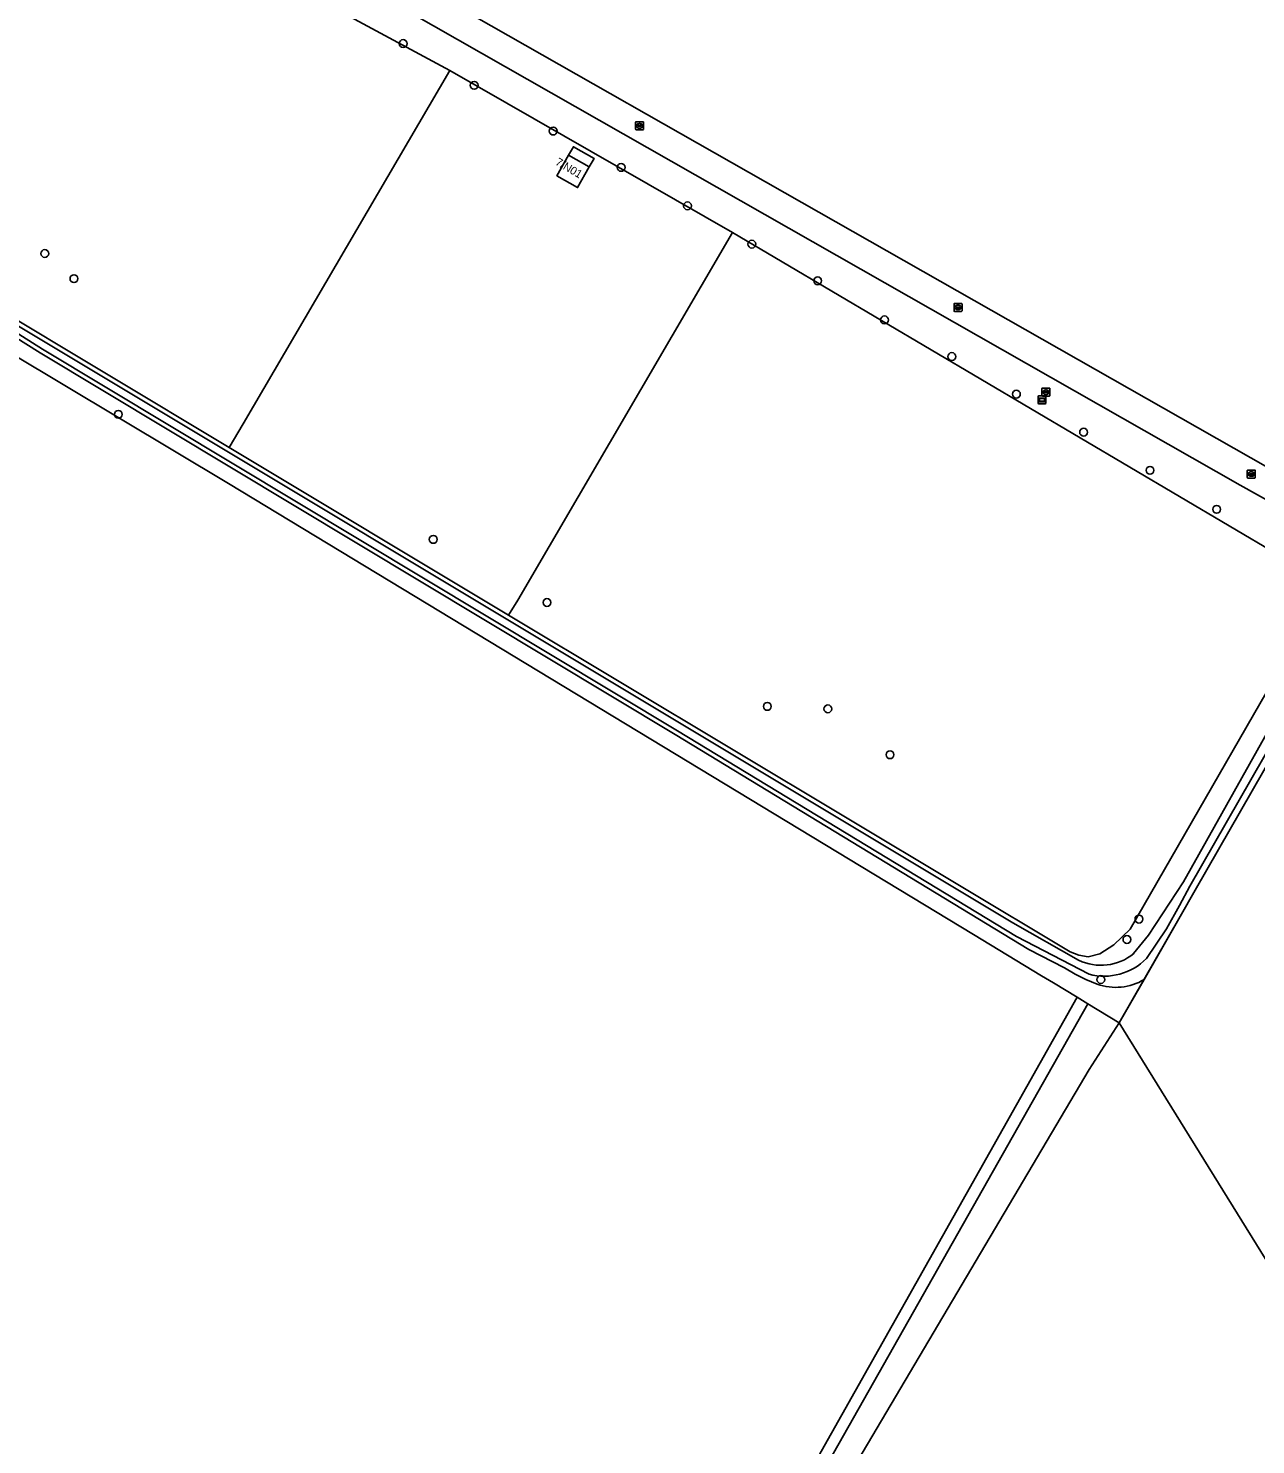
# Model space of a CAD drawing. Extents: x 156502 to 159075, y 384229 to 386100.
# Drawn here: x 157006.8 to 157160.1, y 385363.6 to 385540.6 of the extents above; entities that cross this region are included whole.
import ezdxf

# ---------------------------------------------------------------- set-up
doc = ezdxf.new("R2010")
doc.units = 0
for name, color, linetype in [('IMGEO_Berm_groen', 7, 'Continuous'), ('IMGEO_Boom', 7, 'Continuous'), ('IMGEO_Brandkraan', 7, 'Continuous'), ('IMGEO_Gemengd_bos', 7, 'Continuous'), ('IMGEO_Grasland_agrarisch', 7, 'Continuous'), ('IMGEO_Greppel_droge_sloot', 7, 'Continuous'), ('IMGEO_Groenvoorziening', 7, 'Continuous'), ('IMGEO_Hek', 7, 'Continuous'), ('IMGEO_Loofbos', 7, 'Continuous'), ('IMGEO_Oever', 7, 'Continuous'), ('IMGEO_Pand', 7, 'Continuous'), ('IMGEO_Pand_nummerreeks', 7, 'Continuous'), ('IMGEO_Rijbaan_lokaal_gesloten', 7, 'Continuous'), ('IMGEO_Rioolput', 7, 'Continuous'), ('IMGEO_Verklikker', 7, 'Continuous'), ('IMGEO_Voetpad_open', 7, 'Continuous'), ('IMGEO_Waterloop', 7, 'Continuous')]:
    doc.layers.add(name, color=color, linetype=linetype)

msp = doc.modelspace()

# ---------------------------------------------------------------- linework, layer by layer
at = {"layer": 'IMGEO_Berm_groen'}
msp.add_lwpolyline([(157001.03, 385573.03), (156996.31, 385575.65), (156994.07, 385576.9), (156991.33, 385572.02), (157059.48, 385535.3), (157094.76, 385515.05), (157169.19, 385471.06), (157172.1, 385476.13), (157162.51, 385481.09), (157158.15, 385483.48)], close=True, dxfattribs=at)
at = {"layer": 'IMGEO_Boom'}
for centre in [(157053.64, 385538.65), (157062.51, 385533.44), (157072.38, 385527.72), (157080.86, 385523.18), (157089.15, 385518.38), (157008.89, 385512.42), (157097.18, 385513.6), (157012.53, 385509.29), (157105.4, 385509.02), (157113.75, 385504.13), (157122.16, 385499.55), (157130.22, 385494.86), (157018.07, 385492.33), (157138.61, 385490.1), (157146.9, 385485.34), (157155.23, 385480.47), (157057.4, 385476.71), (157071.6, 385468.83), (157099.12, 385455.85), (157106.68, 385455.54), (157114.44, 385449.81), (157145.52, 385429.28), (157144.02, 385426.73), (157140.76, 385421.73)]:
    msp.add_circle(centre, 0.489, dxfattribs=at)
at = {"layer": 'IMGEO_Brandkraan'}
for p, q in [((157133.41, 385494.68), (157133.41, 385495.53)), ((157133.48, 385495.6), (157134.34, 385495.6)), ((157133.67, 385495.1), (157133.67, 385495.11)), ((157133.71, 385495.15), (157134.11, 385495.15)), ((157134.11, 385495.06), (157133.71, 385495.06)), ((157133.9, 385495.38), (157133.92, 385495.38)), ((157133.92, 385494.82), (157133.9, 385494.82)), ((157134.15, 385495.11), (157134.15, 385495.1)), ((157134.41, 385495.53), (157134.41, 385494.68)), ((157134.34, 385494.6), (157133.48, 385494.6))]:
    msp.add_line(p, q, dxfattribs=at)
for points in [[(157133.41, 385494.68), (157133.41, 385495.53)], [(157133.48, 385495.6), (157134.34, 385495.6)], [(157134.41, 385495.53), (157134.41, 385494.68)], [(157134.34, 385494.6), (157133.48, 385494.6)]]:
    msp.add_lwpolyline(points, dxfattribs=at)
for centre, radius, start, end in [((157133.49, 385495.53), 0.0765, 91.552, 178.448), ((157133.49, 385495.53), 0.0765, 91.552, 178.448), ((157133.71, 385495.11), 0.0403, 85.8775, 175.7526), ((157133.71, 385495.1), 0.0366, 178.938, 274.7102), ((157134.11, 385495.11), 0.0386, 1.7309, 96.639), ((157134.11, 385495.1), 0.043, 264.8664, 352.4533), ((157134.33, 385495.53), 0.0765, 1.552, 88.448), ((157134.33, 385495.53), 0.0765, 1.552, 88.448), ((157133.49, 385494.68), 0.0765, 181.552, 268.448), ((157133.49, 385494.68), 0.0765, 181.552, 268.448), ((157134.33, 385494.68), 0.0765, 271.552, 358.448), ((157134.33, 385494.68), 0.0765, 271.552, 358.448)]:
    msp.add_arc(centre, radius, start, end, dxfattribs=at)
for centre, major_axis, ratio, start_param, end_param in [((157133.9, 385495.1), (-0.387, 0.002), 0.722429, 4.712389, 7.853982), ((157133.92, 385495.1), (-0.39, 0.002), 0.717154, 1.570796, 4.712389)]:
    msp.add_ellipse(centre, major_axis=major_axis, ratio=ratio, start_param=start_param, end_param=end_param, dxfattribs=at)
at = {"layer": 'IMGEO_Gemengd_bos'}
msp.add_lwpolyline([(157191.03, 385500), (157152.55, 385432.88), (157150.67, 385429.59), (157146.17, 385421.74), (157143.05, 385416.31), (157168.42, 385375.4)], dxfattribs=at)
at = {"layer": 'IMGEO_Grasland_agrarisch'}
msp.add_lwpolyline([(157014.02, 385600.24), (157004.36, 385586.62), (157002.14, 385583.66), (156998.46, 385578.63), (156999.74, 385577.82), (157163.72, 385484.49)], dxfattribs=at)
at = {"layer": 'IMGEO_Greppel_droge_sloot'}
for points in [[(157393.36, 385858.05), (157393.11, 385857.61), (157362.75, 385804.11), (157325.82, 385739.17), (157293.92, 385684.22), (157277.51, 385655.56), (157259.26, 385623.71), (157238.62, 385587.75), (157224.85, 385563.79), (157203.07, 385525.9), (157174.27, 385475.36), (157161.25, 385452.05), (157151.08, 385433.93), (157146.7, 385427.27), (157144.86, 385424.97)], [(157146.46, 385424.36), (157148.98, 385428.05), (157150.58, 385430.99), (157151.89, 385433.4), (157190.31, 385500.41), (157270.67, 385640.6), (157287.16, 385669.09), (157334.24, 385750.41), (157371.86, 385817.15), (157394.6, 385857.47)], [(156957.24, 385534.77), (156969.36, 385548.57), (156968.77, 385549.2), (156968.26, 385549.73), (156953.85, 385533.85), (156962.21, 385528.96), (156977.13, 385519.65), (157000.29, 385505.71), (157008.62, 385500.48), (157087.91, 385452.8), (157130.24, 385427.09), (157139.29, 385422.4)], [(157137.99, 385424.15), (157129.78, 385428.82), (157066.52, 385466.78), (157031.64, 385487.72), (156971.16, 385524.01), (156960.67, 385530.59), (156958.05, 385532.14)]]:
    msp.add_lwpolyline(points, dxfattribs=at)
for centre, radius, start, end in [((157140.78, 385429.95), 6.44, 244.2682, 309.3516), ((157141.2, 385429.51), 7.36, 254.9937, 315.6328)]:
    msp.add_arc(centre, radius, start, end, dxfattribs=at)
at = {"layer": 'IMGEO_Groenvoorziening'}
for points in [[(157059.48, 385535.3), (156991.33, 385572.02), (156989.98, 385570.43), (156975.63, 385554.48), (156970.11, 385548.59), (156957.68, 385534.42)], [(157008.33, 385500), (157000, 385505.23), (156976.84, 385519.18), (156961.92, 385528.48), (156952.97, 385533.71), (156952.57, 385531.03), (156952.99, 385531.11), (156953.52, 385530.93), (157000, 385502.8), (157002.27, 385501.42), (157004.67, 385499.97), (157031.83, 385483.7), (157124.85, 385427.36), (157133.37, 385422.2), (157134.84, 385421.31), (157137.81, 385419.52), (157139.14, 385418.7), (157143.05, 385416.31), (157146.17, 385421.74)], [(156958.28, 385532.65), (156960.96, 385531.06), (156971.45, 385524.49), (157031.92, 385488.2), (157033.65, 385491.16), (157059.48, 385535.3)], [(157140.31, 385421.15), (157138.9, 385421.73), (157137.54, 385422.42), (157136.21, 385423.18), (157131.79, 385425.5), (157087.62, 385452.33), (157008.33, 385500)]]:
    msp.add_lwpolyline(points, dxfattribs=at)
msp.add_lwpolyline([(157169.19, 385471.06), (157094.76, 385515.05), (157067.95, 385469.14), (157066.81, 385467.26), (157136.95, 385425.17), (157138.03, 385424.77), (157139.2, 385424.57), (157140.63, 385424.94), (157142.39, 385426.07), (157144.41, 385428.01)], close=True, dxfattribs=at)
msp.add_arc((157142.62, 385427.61), 6.86, 250.3239, 301.1457, dxfattribs=at)
at = {"layer": 'IMGEO_Hek'}
for points in [[(157004.67, 385499.97), (157031.83, 385483.7), (157124.85, 385427.36)], [(157191.03, 385500), (157152.55, 385432.88)], [(157152.55, 385432.88), (157150.67, 385429.59)], [(157150.67, 385429.59), (157143.05, 385416.31)], [(157124.85, 385427.36), (157133.37, 385422.2)], [(157051.69, 385266.61), (157137.81, 385419.52)], [(157137.81, 385419.52), (157139.14, 385418.7)], [(157143.05, 385416.31), (157139.14, 385418.7)]]:
    msp.add_lwpolyline(points, dxfattribs=at)
at = {"layer": 'IMGEO_Loofbos'}
for points in [[(157094.76, 385515.05), (157059.48, 385535.3), (157033.65, 385491.16), (157031.92, 385488.2), (157066.81, 385467.26), (157067.95, 385469.14)], [(157072.84, 385522.13), (157074.31, 385524.73), (157074.9, 385525.77), (157077.49, 385524.31), (157076.89, 385523.27), (157075.43, 385520.67)]]:
    msp.add_lwpolyline(points, close=True, dxfattribs=at)
for points in [[(157098.66, 385347.11), (157139.14, 385418.7), (157137.81, 385419.52), (157134.84, 385421.31), (157133.37, 385422.2), (157124.85, 385427.36), (157031.83, 385483.7), (157004.67, 385499.97), (157002.27, 385501.42), (157000, 385502.8), (156953.52, 385530.93), (156952.99, 385531.11), (156952.57, 385531.03), (156943.32, 385520.77), (156928.3, 385503.39), (156926.66, 385501.65), (156925.39, 385500), (156923.88, 385496.93), (156920.36, 385491), (156916.24, 385485.48)], [(157154.56, 385270.82), (157155.34, 385286.69), (157156.52, 385319.54), (157156.81, 385324.61), (157157.9, 385337.31), (157158.78, 385343.97), (157159.61, 385347.97), (157163.12, 385361.29), (157168.42, 385375.4), (157143.05, 385416.31), (157139.29, 385410.49), (157101.02, 385345.74)]]:
    msp.add_lwpolyline(points, dxfattribs=at)
at = {"layer": 'IMGEO_Oever'}
for points in [[(157392.25, 385858.97), (157329.73, 385750), (157284.2, 385670.89), (157172.1, 385476.13), (157169.19, 385471.06), (157144.41, 385428.01), (157142.39, 385426.07), (157140.63, 385424.94), (157139.2, 385424.57), (157138.03, 385424.77), (157136.95, 385425.17), (157066.81, 385467.26), (157031.92, 385488.2), (156971.45, 385524.49), (156960.96, 385531.06), (156958.28, 385532.65)], [(157144.86, 385424.97), (157146.7, 385427.27), (157151.08, 385433.93), (157161.25, 385452.05), (157174.27, 385475.36), (157203.07, 385525.9), (157224.85, 385563.79), (157238.62, 385587.75), (157259.26, 385623.71), (157277.51, 385655.56), (157293.92, 385684.22), (157325.82, 385739.17), (157362.75, 385804.11), (157393.11, 385857.61), (157393.36, 385858.05)], [(157394.6, 385857.47), (157371.86, 385817.15), (157334.24, 385750.41), (157287.16, 385669.09), (157270.67, 385640.6), (157190.31, 385500.41), (157151.89, 385433.4), (157150.58, 385430.99), (157148.98, 385428.05), (157146.46, 385424.36)], [(157146.17, 385421.74), (157150.67, 385429.59), (157152.55, 385432.88), (157191.03, 385500), (157271.39, 385640.19), (157287.88, 385668.68), (157334.96, 385750), (157372.59, 385816.74), (157395.47, 385857.33)], [(156969.17, 385549.58), (156968.25, 385550.55), (156952.97, 385533.71), (156961.92, 385528.48), (156976.84, 385519.18), (157000, 385505.23), (157008.33, 385500), (157087.62, 385452.33), (157131.79, 385425.5), (157136.21, 385423.18), (157137.54, 385422.42), (157138.9, 385421.73), (157140.31, 385421.15)], [(157139.29, 385422.4), (157130.24, 385427.09), (157087.91, 385452.8), (157008.62, 385500.48), (157000.29, 385505.71), (156977.13, 385519.65), (156962.21, 385528.96), (156953.85, 385533.85), (156968.26, 385549.73), (156968.77, 385549.2), (156969.36, 385548.57), (156957.24, 385534.77)], [(156958.05, 385532.14), (156960.67, 385530.59), (156971.16, 385524.01), (157031.64, 385487.72), (157066.52, 385466.78), (157129.78, 385428.82), (157137.99, 385424.15)]]:
    msp.add_lwpolyline(points, dxfattribs=at)
for centre, radius, start, end in [((157140.78, 385429.95), 6.44, 244.2682, 309.3516), ((157141.2, 385429.51), 7.36, 254.9937, 315.6328), ((157142.62, 385427.61), 6.86, 250.3239, 301.1457)]:
    msp.add_arc(centre, radius, start, end, dxfattribs=at)
at = {"layer": 'IMGEO_Pand'}
msp.add_lwpolyline([(157075.43, 385520.67), (157076.89, 385523.27), (157074.31, 385524.73), (157072.84, 385522.13)], close=True, dxfattribs=at)
at = {"layer": 'IMGEO_Rijbaan_lokaal_gesloten'}
for points in [[(156999.74, 385577.82), (156998.46, 385578.63), (156996.31, 385575.65), (157001.03, 385573.03), (157158.15, 385483.48), (157162.51, 385481.09)], [(157163.72, 385484.49), (156999.74, 385577.82)]]:
    msp.add_lwpolyline(points, dxfattribs=at)
at = {"layer": 'IMGEO_Rioolput'}
for p, q in [((157082.67, 385527.95), (157082.67, 385528.8)), ((157082.74, 385528.87), (157083.59, 385528.87)), ((157082.93, 385528.37), (157082.93, 385528.38)), ((157082.97, 385528.42), (157083.37, 385528.42)), ((157083.16, 385528.65), (157083.18, 385528.65)), ((157083.41, 385528.38), (157083.41, 385528.37)), ((157083.67, 385528.8), (157083.67, 385527.95)), ((157083.59, 385527.87), (157082.74, 385527.87)), ((157083.36, 385528.33), (157082.97, 385528.33)), ((157083.18, 385528.09), (157083.15, 385528.09)), ((157122.43, 385505.27), (157122.43, 385506.12)), ((157122.5, 385506.19), (157123.35, 385506.19)), ((157122.68, 385505.69), (157122.68, 385505.7)), ((157123.12, 385505.65), (157122.72, 385505.65)), ((157122.73, 385505.74), (157123.13, 385505.74)), ((157122.91, 385505.97), (157122.94, 385505.97)), ((157122.94, 385505.41), (157122.91, 385505.41)), ((157123.17, 385505.7), (157123.17, 385505.69)), ((157123.43, 385506.12), (157123.43, 385505.27)), ((157123.35, 385505.19), (157122.5, 385505.19)), ((157159.05, 385484.45), (157159.05, 385485.3)), ((157159.13, 385485.37), (157159.98, 385485.37)), ((157159.98, 385484.37), (157159.13, 385484.37)), ((157159.31, 385484.87), (157159.31, 385484.88)), ((157159.35, 385484.92), (157159.75, 385484.92)), ((157159.75, 385484.83), (157159.35, 385484.83)), ((157159.54, 385485.15), (157159.57, 385485.15)), ((157159.56, 385484.59), (157159.54, 385484.59)), ((157159.8, 385484.88), (157159.8, 385484.87)), ((157160.05, 385485.3), (157160.05, 385484.45))]:
    msp.add_line(p, q, dxfattribs=at)
for points in [[(157082.67, 385527.95), (157082.67, 385528.8)], [(157082.74, 385528.87), (157083.59, 385528.87)], [(157083.67, 385528.8), (157083.67, 385527.95)], [(157083.59, 385527.87), (157082.74, 385527.87)], [(157122.43, 385505.27), (157122.43, 385506.12)], [(157122.5, 385506.19), (157123.35, 385506.19)], [(157123.43, 385506.12), (157123.43, 385505.27)], [(157123.35, 385505.19), (157122.5, 385505.19)], [(157159.05, 385484.45), (157159.05, 385485.3)], [(157159.13, 385485.37), (157159.98, 385485.37)], [(157159.98, 385484.37), (157159.13, 385484.37)], [(157160.05, 385485.3), (157160.05, 385484.45)]]:
    msp.add_lwpolyline(points, dxfattribs=at)
for centre, radius, start, end in [((157082.74, 385528.8), 0.0765, 91.552, 178.448), ((157082.74, 385528.8), 0.0765, 91.552, 178.448), ((157082.97, 385528.38), 0.0403, 85.8775, 175.7526), ((157083.37, 385528.38), 0.0386, 1.7309, 96.639), ((157083.59, 385528.8), 0.0765, 1.552, 88.448), ((157083.59, 385528.8), 0.0765, 1.552, 88.448), ((157082.74, 385527.95), 0.0765, 181.552, 268.448), ((157082.74, 385527.95), 0.0765, 181.552, 268.448), ((157082.96, 385528.37), 0.0366, 178.938, 274.7102), ((157083.37, 385528.37), 0.043, 264.8664, 352.4533), ((157083.59, 385527.95), 0.0765, 271.552, 358.448), ((157083.59, 385527.95), 0.0765, 271.552, 358.448), ((157122.5, 385506.12), 0.0765, 91.552, 178.448), ((157122.5, 385506.12), 0.0765, 91.552, 178.448), ((157122.73, 385505.7), 0.0403, 85.8775, 175.7526), ((157122.72, 385505.69), 0.0366, 178.938, 274.7102), ((157123.13, 385505.69), 0.043, 264.8664, 352.4533), ((157123.13, 385505.7), 0.0386, 1.7309, 96.639), ((157123.35, 385506.12), 0.0765, 1.552, 88.448), ((157123.35, 385506.12), 0.0765, 1.552, 88.448), ((157122.5, 385505.27), 0.0765, 181.552, 268.448), ((157122.5, 385505.27), 0.0765, 181.552, 268.448), ((157123.35, 385505.27), 0.0765, 271.552, 358.448), ((157123.35, 385505.27), 0.0765, 271.552, 358.448), ((157159.13, 385485.3), 0.0765, 91.552, 178.448), ((157159.13, 385485.3), 0.0765, 91.552, 178.448), ((157159.13, 385484.45), 0.0765, 181.552, 268.448), ((157159.13, 385484.45), 0.0765, 181.552, 268.448), ((157159.35, 385484.88), 0.0403, 85.8775, 175.7526), ((157159.35, 385484.87), 0.0366, 178.938, 274.7102), ((157159.76, 385484.88), 0.0386, 1.7309, 96.639), ((157159.75, 385484.87), 0.043, 264.8664, 352.4533), ((157159.98, 385485.3), 0.0765, 1.552, 88.448), ((157159.98, 385485.3), 0.0765, 1.552, 88.448), ((157159.98, 385484.45), 0.0765, 271.552, 358.448), ((157159.98, 385484.45), 0.0765, 271.552, 358.448)]:
    msp.add_arc(centre, radius, start, end, dxfattribs=at)
for centre, major_axis, ratio, start_param, end_param in [((157083.15, 385528.37), (-0.387, 0.002), 0.722429, 4.712389, 7.853982), ((157083.18, 385528.37), (-0.39, 0.002), 0.717154, 1.570796, 4.712389), ((157122.91, 385505.69), (-0.387, 0.002), 0.722429, 4.712389, 7.853982), ((157122.94, 385505.69), (-0.39, 0.002), 0.717154, 1.570796, 4.712389), ((157159.54, 385484.87), (-0.387, 0.002), 0.722429, 4.712389, 7.853982), ((157159.56, 385484.87), (-0.39, 0.002), 0.717154, 1.570796, 4.712389)]:
    msp.add_ellipse(centre, major_axis=major_axis, ratio=ratio, start_param=start_param, end_param=end_param, dxfattribs=at)
at = {"layer": 'IMGEO_Verklikker'}
for p, q in [((157132.92, 385493.74), (157132.92, 385494.54)), ((157132.92, 385494.54), (157132.92, 385493.74)), ((157133.02, 385494.64), (157133.81, 385494.64)), ((157133.81, 385494.64), (157133.02, 385494.64)), ((157133.81, 385493.64), (157133.02, 385493.64)), ((157133.02, 385493.64), (157133.81, 385493.64)), ((157133.91, 385494.54), (157133.91, 385493.74)), ((157133.91, 385493.74), (157133.91, 385494.54))]:
    msp.add_line(p, q, dxfattribs=at)
for points in [[(157133.02, 385494.37), (157133.81, 385494.37), (157133.81, 385493.91), (157133.02, 385493.91), (157133.02, 385494.37)], [(157133.09, 385494.31), (157133.09, 385493.97), (157133.74, 385493.97), (157133.74, 385494.31), (157133.09, 385494.31)]]:
    msp.add_lwpolyline(points, dxfattribs=at)
for centre, start, end in [((157133.02, 385494.54), 90, 180), ((157133.02, 385494.54), 90, 180), ((157133.02, 385493.74), 180, 270), ((157133.02, 385493.74), 180, 270), ((157133.81, 385494.54), 0, 90), ((157133.81, 385494.54), 360, 90), ((157133.81, 385493.74), 270, 0), ((157133.81, 385493.74), 270, 0)]:
    msp.add_arc(centre, 0.1, start, end, dxfattribs=at)
at = {"layer": 'IMGEO_Voetpad_open'}
msp.add_lwpolyline([(157074.31, 385524.73), (157076.89, 385523.27), (157077.49, 385524.31), (157074.9, 385525.77)], close=True, dxfattribs=at)
at = {"layer": 'IMGEO_Waterloop'}
msp.add_lwpolyline([(157101.02, 385345.74), (157139.29, 385410.49), (157143.05, 385416.31), (157139.14, 385418.7), (157098.66, 385347.11)], dxfattribs=at)

# ---------------------------------------------------------------- texts
at = {"layer": 'IMGEO_Pand_nummerreeks'}
msp.add_text('7/N01', height=1, rotation=329.4379, dxfattribs=at).set_placement((157072.56, 385523.59))

doc.saveas('drawing.dxf')
